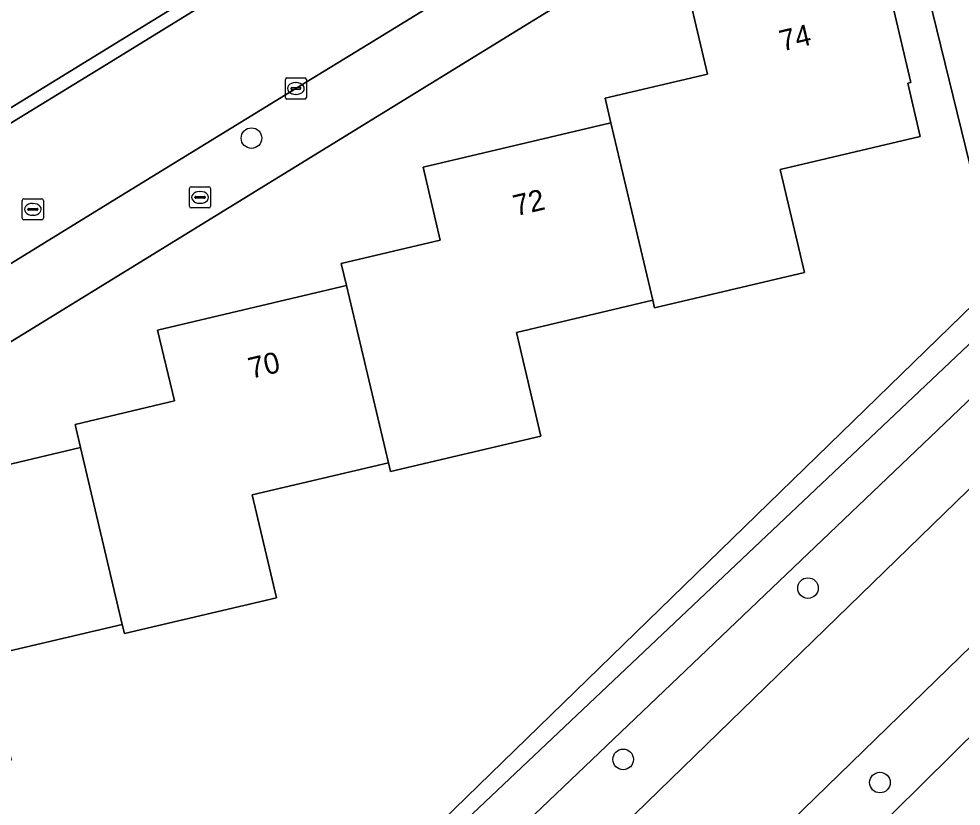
# Model space of a CAD drawing. Extents: x 157648 to 158502, y 379212 to 380938.
# Drawn here: x 158282.88 to 158327.67, y 380514.11 to 380551.53 of the extents above; entities that cross this region are included whole.
import ezdxf

# ---------------------------------------------------------------- set-up
doc = ezdxf.new("R2010")
doc.units = 0
for name, color, linetype in [('IMGEO_Boom', 7, 'Continuous'), ('IMGEO_Brandkraan', 7, 'Continuous'), ('IMGEO_Erf', 7, 'Continuous'), ('IMGEO_Groenvoorziening', 7, 'Continuous'), ('IMGEO_Kolk', 7, 'Continuous'), ('IMGEO_Pand', 7, 'Continuous'), ('IMGEO_Pand_nummerreeks', 7, 'Continuous'), ('IMGEO_Rijbaan_lokaal_gesloten', 7, 'Continuous'), ('IMGEO_Rijbaan_lokaal_open', 7, 'Continuous'), ('IMGEO_Rioolput', 7, 'Continuous'), ('IMGEO_Voetpad_open', 7, 'Continuous'), ('IMGEO_Waterloop', 7, 'Continuous')]:
    doc.layers.add(name, color=color, linetype=linetype)

msp = doc.modelspace()

# ---------------------------------------------------------------- linework, layer by layer
at = {"layer": 'IMGEO_Boom'}
for centre in [(158293.94, 380545.859), (158320.389, 380524.472), (158311.606, 380516.33), (158323.809, 380515.229)]:
    msp.add_circle(centre, 0.489, dxfattribs=at)
at = {"layer": 'IMGEO_Brandkraan'}
for p, q in [((158290.994, 380542.616), (158290.994, 380543.468)), ((158291.069, 380543.542), (158291.921, 380543.542)), ((158291.482, 380543.322), (158291.507, 380543.322)), ((158291.995, 380543.468), (158291.995, 380542.616)), ((158291.253, 380543.036), (158291.253, 380543.048)), ((158291.691, 380542.999), (158291.293, 380542.999)), ((158291.296, 380543.085), (158291.694, 380543.085)), ((158291.737, 380543.048), (158291.737, 380543.036)), ((158291.921, 380542.542), (158291.069, 380542.542)), ((158291.505, 380542.762), (158291.48, 380542.762))]:
    msp.add_line(p, q, dxfattribs=at)
for points in [[(158290.994, 380542.616), (158290.994, 380543.468)], [(158291.069, 380543.542), (158291.921, 380543.542)], [(158291.995, 380543.468), (158291.995, 380542.616)], [(158291.921, 380542.542), (158291.069, 380542.542)]]:
    msp.add_lwpolyline(points, dxfattribs=at)
for centre, radius, start, end in [((158291.071, 380543.466), 0.0765, 91.552, 178.448), ((158291.071, 380543.466), 0.0765, 91.552, 178.448), ((158291.919, 380543.466), 0.0765, 1.552, 88.448), ((158291.919, 380543.466), 0.0765, 1.552, 88.448), ((158291.293, 380543.045), 0.0403, 85.8775, 175.7526), ((158291.29, 380543.035), 0.0366, 178.938, 274.7102), ((158291.694, 380543.042), 0.043, 264.8664, 352.4533), ((158291.698, 380543.047), 0.0386, 1.7309, 96.639), ((158291.071, 380542.618), 0.0765, 181.552, 268.448), ((158291.071, 380542.618), 0.0765, 181.552, 268.448), ((158291.919, 380542.618), 0.0765, 271.552, 358.448), ((158291.919, 380542.618), 0.0765, 271.552, 358.448)]:
    msp.add_arc(centre, radius, start, end, dxfattribs=at)
for centre, major_axis, ratio, start_param, end_param in [((158291.481, 380543.042), (-0.387, 0.002), 0.722429, 4.712389, 7.853982), ((158291.506, 380543.042), (-0.39, 0.002), 0.717154, 1.570796, 4.712389)]:
    msp.add_ellipse(centre, major_axis=major_axis, ratio=ratio, start_param=start_param, end_param=end_param, dxfattribs=at)
at = {"layer": 'IMGEO_Erf'}
for points in [[(158255.365, 380530.629), (158313.789, 380566.552)], [(158319.496, 380558.936), (158263.701, 380524.634), (158257.585, 380520.788), (158257.469, 380520.719), (158257.353, 380520.65), (158261.062, 380505.621), (158262.697, 380504.321), (158264.187, 380502.857), (158265.516, 380501.245), (158266.367, 380500), (158267.425, 380498.089), (158268.197, 380496.241), (158268.772, 380494.324), (158269.143, 380492.356), (158269.406, 380490.783), (158269.906, 380488.917), (158270.597, 380487.114), (158271.474, 380485.392), (158272.525, 380483.772), (158289.215, 380500), (158329.422, 380539.101), (158325.742, 380554.195), (158320.483, 380559.775)], [(158276.998, 380529.064), (158285.818, 380531.146), (158285.557, 380532.25), (158290.277, 380533.364), (158289.481, 380536.737), (158298.457, 380538.857), (158298.209, 380539.905), (158302.915, 380541.015), (158302.099, 380544.472), (158311.024, 380546.579), (158310.747, 380547.756), (158315.614, 380548.904), (158314.809, 380552.314)], [(158324.409, 380552.21), (158325.283, 380548.506), (158325.129, 380548.469), (158325.728, 380545.932), (158319.072, 380544.361), (158320.226, 380539.474), (158313.099, 380537.792), (158313.014, 380538.151), (158306.535, 380536.622), (158307.697, 380531.7), (158300.545, 380530.011), (158300.446, 380530.431), (158293.97, 380528.902), (158295.125, 380524.011), (158287.904, 380522.307), (158287.8, 380522.749), (158281.366, 380521.23)]]:
    msp.add_lwpolyline(points, dxfattribs=at)
at = {"layer": 'IMGEO_Groenvoorziening'}
for points in [[(158320.483, 380559.775), (158325.742, 380554.195), (158329.422, 380539.101), (158334.137, 380543.912)], [(158334.137, 380543.912), (158329.422, 380539.101), (158289.215, 380500), (158272.525, 380483.772), (158271.474, 380485.392), (158270.597, 380487.114), (158269.906, 380488.917), (158269.406, 380490.783), (158269.143, 380492.356), (158268.772, 380494.324), (158268.197, 380496.241), (158267.425, 380498.089), (158266.367, 380500), (158265.516, 380501.245), (158264.187, 380502.857), (158262.697, 380504.321), (158261.062, 380505.621), (158257.353, 380520.65)], [(158289.923, 380500), (158330.921, 380538.776)], [(158351.008, 380525.41), (158343.973, 380533.099), (158310.494, 380500), (158310.095, 380499.607)]]:
    msp.add_lwpolyline(points, dxfattribs=at)
for points in [[(158332.358, 380537.527), (158293.02, 380500), (158274.224, 380482.069), (158273.465, 380481.728), (158270.73, 380478.676), (158272.883, 380475.555), (158277.441, 380479.984), (158298.039, 380500), (158339.285, 380540.082), (158336.691, 380542), (158332.462, 380538.012)], [(158343.973, 380533.099), (158342.036, 380535.216), (158341.944, 380535.126), (158305.818, 380500), (158282.116, 380476.953), (158279.097, 380474.018), (158278.68, 380473.614), (158280.362, 380471.441), (158280.476, 380471.294), (158280.589, 380471.146), (158284.909, 380475.143), (158286.353, 380476.479), (158286.849, 380477.187), (158310.095, 380499.607), (158310.494, 380500)]]:
    msp.add_lwpolyline(points, close=True, dxfattribs=at)
at = {"layer": 'IMGEO_Kolk'}
for p, q in [((158295.625, 380548.715), (158296.477, 380548.715)), ((158295.55, 380547.789), (158295.55, 380548.641)), ((158295.852, 380548.258), (158296.25, 380548.258)), ((158296.038, 380548.495), (158296.063, 380548.495)), ((158296.551, 380548.641), (158296.551, 380547.789)), ((158295.809, 380548.209), (158295.809, 380548.221)), ((158296.247, 380548.172), (158295.849, 380548.172)), ((158296.061, 380547.935), (158296.036, 380547.935)), ((158296.293, 380548.221), (158296.293, 380548.209)), ((158296.477, 380547.715), (158295.625, 380547.715))]:
    msp.add_line(p, q, dxfattribs=at)
for points in [[(158295.625, 380548.715), (158296.477, 380548.715)], [(158295.55, 380547.789), (158295.55, 380548.641)], [(158296.551, 380548.641), (158296.551, 380547.789)], [(158296.477, 380547.715), (158295.625, 380547.715)]]:
    msp.add_lwpolyline(points, dxfattribs=at)
for centre, radius, start, end in [((158295.627, 380548.639), 0.0765, 91.552, 178.448), ((158295.627, 380548.639), 0.0765, 91.552, 178.448), ((158296.475, 380548.639), 0.0765, 1.552, 88.448), ((158296.475, 380548.639), 0.0765, 1.552, 88.448), ((158295.849, 380548.218), 0.0403, 85.8775, 175.7526), ((158296.254, 380548.22), 0.0386, 1.7309, 96.639), ((158295.846, 380548.208), 0.0366, 178.938, 274.7102), ((158296.25, 380548.215), 0.043, 264.8664, 352.4533), ((158295.627, 380547.791), 0.0765, 181.552, 268.448), ((158295.627, 380547.791), 0.0765, 181.552, 268.448), ((158296.475, 380547.791), 0.0765, 271.552, 358.448), ((158296.475, 380547.791), 0.0765, 271.552, 358.448)]:
    msp.add_arc(centre, radius, start, end, dxfattribs=at)
for centre, major_axis, ratio, start_param, end_param in [((158296.037, 380548.215), (-0.387, 0.002), 0.722429, 4.712389, 7.853982), ((158296.062, 380548.215), (-0.39, 0.002), 0.717154, 1.570796, 4.712389)]:
    msp.add_ellipse(centre, major_axis=major_axis, ratio=ratio, start_param=start_param, end_param=end_param, dxfattribs=at)
at = {"layer": 'IMGEO_Pand'}
for points in [[(158311.024, 380546.579), (158313.014, 380538.151), (158313.099, 380537.792), (158320.226, 380539.474), (158319.072, 380544.361), (158325.728, 380545.932), (158325.129, 380548.469), (158325.283, 380548.506), (158324.409, 380552.21), (158324.184, 380551.998), (158323.618, 380554.394), (158314.809, 380552.314), (158315.614, 380548.904), (158310.747, 380547.756)], [(158298.457, 380538.857), (158300.446, 380530.431), (158300.545, 380530.011), (158307.697, 380531.7), (158306.535, 380536.622), (158313.014, 380538.151), (158311.024, 380546.579), (158302.099, 380544.472), (158302.915, 380541.015), (158298.209, 380539.905)], [(158287.8, 380522.749), (158287.904, 380522.307), (158295.125, 380524.011), (158293.97, 380528.902), (158300.446, 380530.431), (158298.457, 380538.857), (158289.481, 380536.737), (158290.277, 380533.364), (158285.557, 380532.25), (158285.818, 380531.146)], [(158287.8, 380522.749), (158285.818, 380531.146), (158276.998, 380529.064), (158277.785, 380525.73), (158273.01, 380524.603), (158273.263, 380523.53), (158275.292, 380514.936), (158275.366, 380514.621), (158282.528, 380516.311), (158281.366, 380521.23)]]:
    msp.add_lwpolyline(points, close=True, dxfattribs=at)
at = {"layer": 'IMGEO_Rijbaan_lokaal_gesloten'}
msp.add_lwpolyline([(158305.818, 380500), (158341.944, 380535.126), (158342.036, 380535.216), (158343.552, 380536.694), (158368.152, 380560.765), (158370.231, 380562.8), (158399.1, 380591.047), (158395.1, 380595.292), (158340.902, 380541.658), (158340.139, 380540.911), (158339.285, 380540.082), (158298.039, 380500)], dxfattribs=at)
at = {"layer": 'IMGEO_Rijbaan_lokaal_open'}
for points in [[(158314.118, 380566.039), (158287.044, 380549.358), (158283.176, 380546.981), (158274.251, 380541.515), (158269.107, 380538.35), (158258.895, 380532.075), (158255.673, 380530.111), (158255.474, 380529.996)], [(158258.475, 380525.117), (158258.671, 380525.235), (158261.874, 380527.217), (158271.47, 380533.125), (158274.688, 380535.092), (158284.111, 380540.882), (158287.327, 380542.854), (158296.248, 380548.339), (158299.467, 380550.309), (158309.243, 380556.306), (158312.474, 380558.276), (158318.985, 380562.272)]]:
    msp.add_lwpolyline(points, dxfattribs=at)
at = {"layer": 'IMGEO_Rioolput'}
for p, q in [((158283.048, 380542.046), (158283.048, 380542.898)), ((158283.123, 380542.972), (158283.975, 380542.972)), ((158284.049, 380542.898), (158284.049, 380542.046)), ((158283.307, 380542.466), (158283.307, 380542.478)), ((158283.745, 380542.429), (158283.347, 380542.429)), ((158283.35, 380542.515), (158283.748, 380542.515)), ((158283.536, 380542.752), (158283.561, 380542.752)), ((158283.791, 380542.478), (158283.791, 380542.466)), ((158283.559, 380542.192), (158283.534, 380542.192)), ((158283.975, 380541.972), (158283.123, 380541.972))]:
    msp.add_line(p, q, dxfattribs=at)
for points in [[(158283.048, 380542.046), (158283.048, 380542.898)], [(158283.123, 380542.972), (158283.975, 380542.972)], [(158284.049, 380542.898), (158284.049, 380542.046)], [(158283.975, 380541.972), (158283.123, 380541.972)]]:
    msp.add_lwpolyline(points, dxfattribs=at)
for centre, radius, start, end in [((158283.125, 380542.896), 0.0765, 91.552, 178.448), ((158283.125, 380542.896), 0.0765, 91.552, 178.448), ((158283.973, 380542.896), 0.0765, 1.552, 88.448), ((158283.973, 380542.896), 0.0765, 1.552, 88.448), ((158283.347, 380542.475), 0.0403, 85.8775, 175.7526), ((158283.344, 380542.465), 0.0366, 178.938, 274.7102), ((158283.748, 380542.472), 0.043, 264.8664, 352.4533), ((158283.752, 380542.477), 0.0386, 1.7309, 96.639), ((158283.125, 380542.048), 0.0765, 181.552, 268.448), ((158283.125, 380542.048), 0.0765, 181.552, 268.448), ((158283.973, 380542.048), 0.0765, 271.552, 358.448), ((158283.973, 380542.048), 0.0765, 271.552, 358.448)]:
    msp.add_arc(centre, radius, start, end, dxfattribs=at)
for centre, major_axis, ratio, start_param, end_param in [((158283.535, 380542.472), (-0.387, 0.002), 0.722429, 4.712389, 7.853982), ((158283.56, 380542.472), (-0.39, 0.002), 0.717154, 1.570796, 4.712389)]:
    msp.add_ellipse(centre, major_axis=major_axis, ratio=ratio, start_param=start_param, end_param=end_param, dxfattribs=at)
at = {"layer": 'IMGEO_Voetpad_open'}
for points in [[(158313.789, 380566.552), (158255.365, 380530.629)], [(158255.474, 380529.996), (158255.673, 380530.111), (158258.895, 380532.075), (158269.107, 380538.35), (158274.251, 380541.515), (158283.176, 380546.981), (158287.044, 380549.358), (158314.118, 380566.039)], [(158318.985, 380562.272), (158312.474, 380558.276), (158309.243, 380556.306), (158299.467, 380550.309), (158296.248, 380548.339), (158287.327, 380542.854), (158284.111, 380540.882), (158274.688, 380535.092), (158271.47, 380533.125), (158261.874, 380527.217), (158258.671, 380525.235), (158258.475, 380525.117)], [(158263.701, 380524.634), (158319.496, 380558.936)]]:
    msp.add_lwpolyline(points, dxfattribs=at)
at = {"layer": 'IMGEO_Waterloop'}
for points in [[(158330.921, 380538.776), (158289.923, 380500)], [(158293.02, 380500), (158332.358, 380537.527)]]:
    msp.add_lwpolyline(points, dxfattribs=at)

# ---------------------------------------------------------------- texts
at = {"layer": 'IMGEO_Pand_nummerreeks'}
for s, rotation, p in [('74', 13.2855, (158319.163, 380549.972)), ('72', 13.2831, (158306.508, 380542.142)), ('70', 13.2889, (158293.922, 380534.415))]:
    msp.add_text(s, height=1, rotation=rotation, dxfattribs=at).set_placement(p)

doc.saveas('drawing.dxf')
